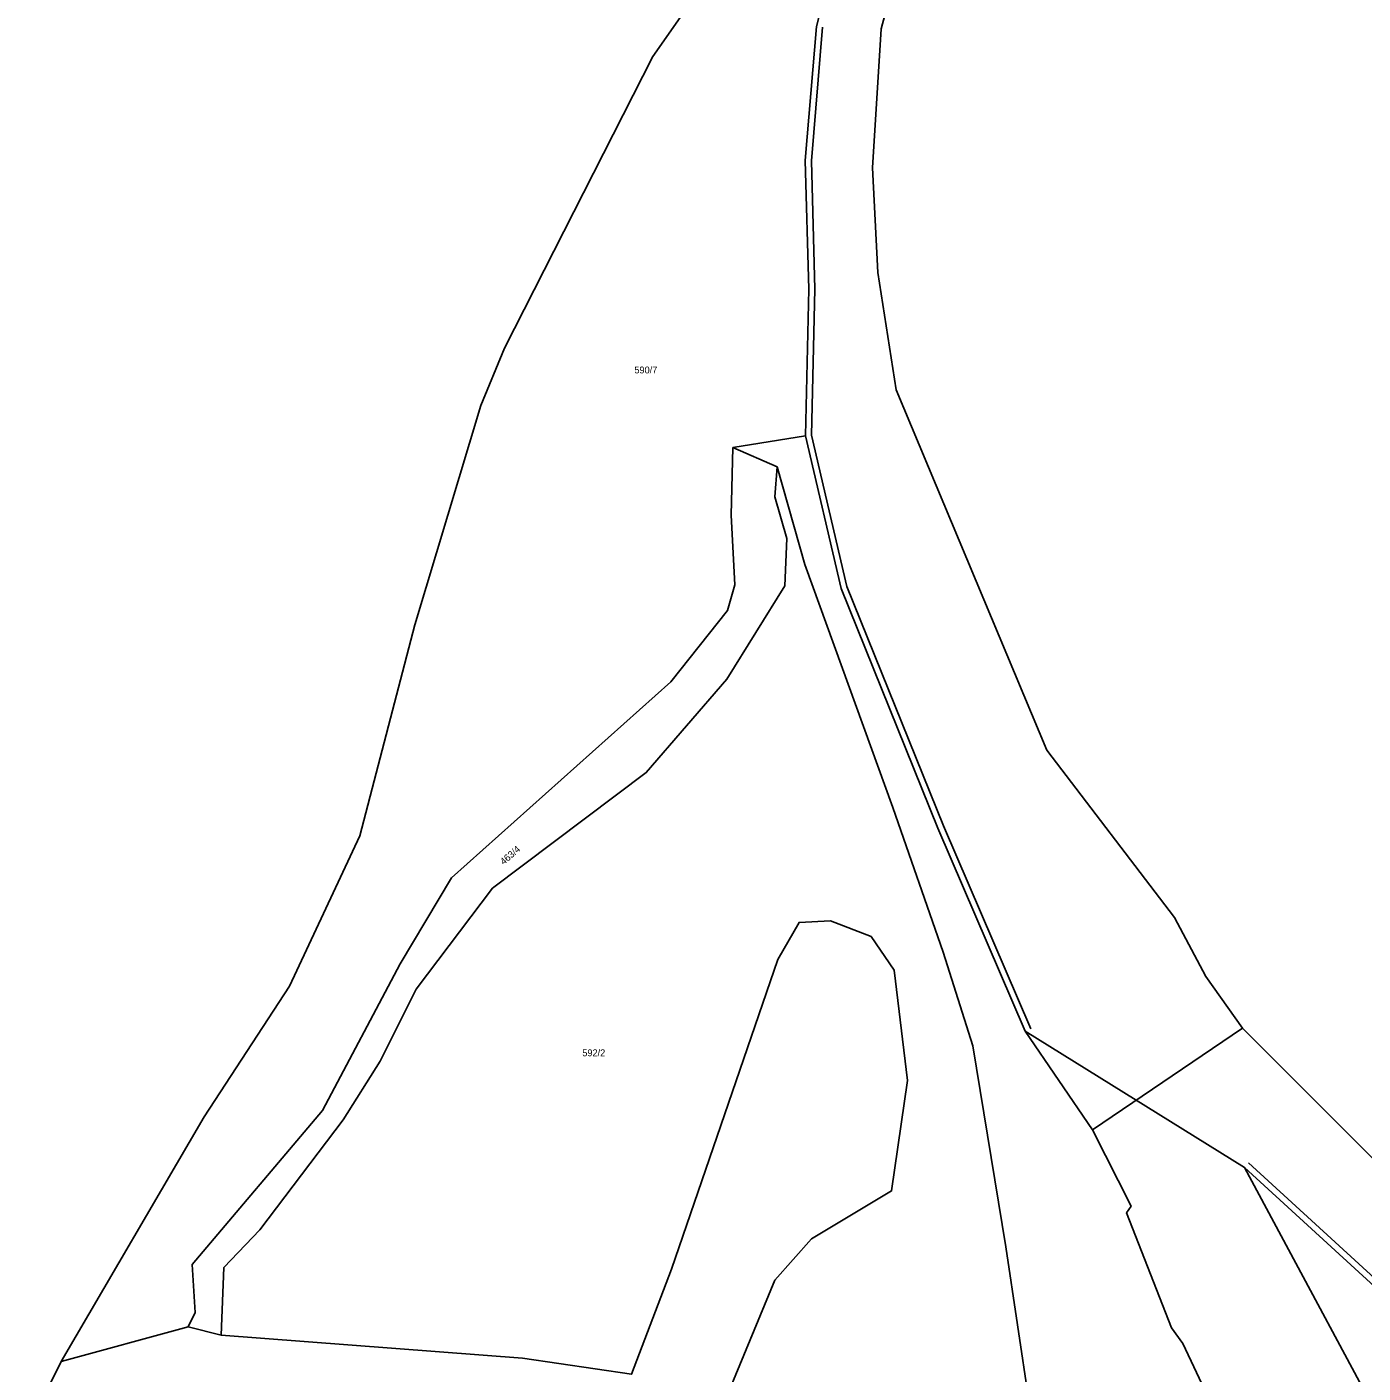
# Model space of a CAD drawing. Extents: x -882150 to -879379, y -1022570 to -1019819.
# Drawn here: x -880740.4 to -880409, y -1022397.8 to -1022063.9 of the extents above; entities that cross this region are included whole.
import ezdxf

# ---------------------------------------------------------------- set-up
doc = ezdxf.new("R2010")
doc.units = 0
for name, color, linetype in [('Hranice parcel', 7, 'Continuous'), ('Parcelní čísla', 7, 'Continuous'), ('Vnitřní kresba', 7, 'Continuous')]:
    doc.layers.add(name, color=color, linetype=linetype)

msp = doc.modelspace()

# ---------------------------------------------------------------- linework, layer by layer
at = {"layer": 'Hranice parcel'}
for p, q in [((-880565.37, -1022168.2), (-880547.31, -1022165.35)), ((-880554.33, -1022173.06), (-880565.37, -1022168.2)), ((-880438.9, -1022312.23), (-880476.08, -1022337.43)), ((-880391.99, -1022359.17), (-880438.9, -1022312.23)), ((-880731.91, -1022394.96), (-880700.41, -1022386.34)), ((-880700.41, -1022386.34), (-880692.24, -1022388.39))]:
    msp.add_line(p, q, dxfattribs=at)
for points in [[(-880481.62, -1021946.61), (-880497.56, -1021965.83), (-880512.49, -1021990.16), (-880523.44, -1022009.43), (-880538.87, -1022041.47), (-880544.54, -1022063.85), (-880547.35, -1022097.08), (-880546.45, -1022128.98), (-880547.31, -1022165.35)], [(-880438.9, -1022312.23), (-880448.03, -1022299.45), (-880455.75, -1022284.78), (-880487.48, -1022243.34), (-880524.79, -1022153.92), (-880529.34, -1022124.84), (-880530.7, -1022098.83), (-880528.56, -1022064.4), (-880524.89, -1022050.76), (-880519.28, -1022036.32), (-880479.95, -1021972.5), (-880463.94, -1021954.07), (-880458.37, -1021949.23)], [(-880731.91, -1022394.96), (-880696.51, -1022334.22), (-880675.29, -1022301.87), (-880657.9, -1022264.58), (-880644.21, -1022212.25), (-880627.87, -1022157.84), (-880621.99, -1022143.56), (-880585.18, -1022071.28), (-880571.42, -1022051.57), (-880545.28, -1022021.02), (-880540.47, -1022015.14)], [(-880547.31, -1022165.35), (-880538.49, -1022203.18), (-880514.44, -1022262.64), (-880492.79, -1022312.99), (-880476.08, -1022337.43)], [(-880565.37, -1022168.2), (-880565.77, -1022185.03), (-880564.87, -1022202.27), (-880566.64, -1022208.65), (-880580.71, -1022226.39), (-880635.16, -1022274.97), (-880647.83, -1022296.26), (-880667.13, -1022332.7), (-880699.48, -1022370.88), (-880698.68, -1022382.77), (-880700.41, -1022386.34)], [(-880692.24, -1022388.39), (-880691.58, -1022371.6), (-880682.69, -1022362.27), (-880662, -1022335), (-880652.85, -1022320.4), (-880643.9, -1022302.61), (-880624.94, -1022277.51), (-880586.83, -1022248.86), (-880566.84, -1022225.68), (-880552.45, -1022202.57), (-880551.91, -1022190.8), (-880554.94, -1022180.44), (-880554.33, -1022173.06)], [(-880554.33, -1022173.06), (-880547.49, -1022197.27), (-880525.62, -1022257.49), (-880513.19, -1022293.42), (-880505.82, -1022316.63), (-880497.62, -1022366.49), (-880491.79, -1022405.22), (-880566.15, -1022401.94), (-880554.94, -1022374.73), (-880545.82, -1022364.54), (-880525.96, -1022352.62), (-880521.99, -1022325.21), (-880525.29, -1022297.87), (-880531.04, -1022289.54), (-880541.07, -1022285.64), (-880548.9, -1022286.02), (-880554.17, -1022295.26), (-880580.55, -1022371.99), (-880590.44, -1022398.07), (-880617.48, -1022394.1), (-880692.24, -1022388.39)], [(-880476.08, -1022337.43), (-880466.52, -1022356.43), (-880467.65, -1022358.04), (-880456.49, -1022386.58), (-880453.69, -1022390.45), (-880439.48, -1022420.61), (-880434.77, -1022431.18), (-880433.13, -1022437.44), (-880432.42, -1022470.88), (-880432.04, -1022486.25), (-880448.2, -1022485.14), (-880716.03, -1022466.72), (-880763.82, -1022463.43)], [(-880404.24, -1022530.56), (-880404.73, -1022508.83), (-880392.77, -1022456.11), (-880397.13, -1022423.7), (-880438.43, -1022346.79), (-880406.13, -1022376.33), (-880395.66, -1022384.1), (-880306.08, -1022468.64), (-880286.2, -1022489.18), (-880275.92, -1022500.64), (-880267.29, -1022514.55), (-880260.67, -1022530.6), (-880256.57, -1022546.88), (-880254.74, -1022558.34), (-880254.4, -1022569)], [(-880763.82, -1022463.43), (-880755, -1022441.07), (-880731.91, -1022394.96)]]:
    msp.add_lwpolyline(points, dxfattribs=at)
at = {"layer": 'Vnitřní kresba'}
for p, q in [((-880545.85, -1022097.13), (-880543.05, -1022063.98)), ((-880544.95, -1022128.99), (-880545.85, -1022097.13)), ((-880545.81, -1022165.2), (-880544.95, -1022128.99)), ((-880537.06, -1022202.73), (-880545.81, -1022165.2)), ((-880513.05, -1022262.07), (-880537.06, -1022202.73)), ((-880491.41, -1022312.4), (-880513.05, -1022262.07)), ((-880438.43, -1022346.79), (-880492.79, -1022312.99)), ((-880405.18, -1022375.17), (-880437.42, -1022345.68))]:
    msp.add_line(p, q, dxfattribs=at)

# ---------------------------------------------------------------- texts
at = {"layer": 'Parcelní čísla'}
for s, p in [('590/7', (-880589.75, -1022149.85)), ('592/2', (-880602.67, -1022319.22))]:
    msp.add_text(s, height=1.7, dxfattribs=at).set_placement(p)
msp.add_text('463/4', height=1.7, rotation=41, dxfattribs=at).set_placement((-880622.172, -1022271.851))

doc.saveas('drawing.dxf')
